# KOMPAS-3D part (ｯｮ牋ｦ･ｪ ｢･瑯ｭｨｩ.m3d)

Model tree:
1. Эскиз:1
2. Операция выдавливания:1
     Расстояние 1 = 8
3. Эскиз:2
4. Операция выдавливания:2
     Расстояние 1 = 1
5. Эскиз:3
6. Операция выдавливания:3
     Расстояние 1 = 2.5; Угол 1 = 8
7. Эскиз:4
8. Вырезать элемент выдавливания:1
     Расстояние 1 = 20
9. Эскиз:5
10. Вырезать элемент выдавливания:2
     Расстояние 1 = 3; Угол 1 = 19
11. Скругление:1
     Радиус = 1
12. Скругление:2
     Радиус = 1
13. Скругление:3
     Радиус = 1
14. Эскиз:6
15. Эскиз:7
16. Вырезать элемент выдавливания:3
     Расстояние 1 = 2.5
17. Эскиз:8
18. Вырезать элемент выдавливания:4
     Расстояние 1 = 42
